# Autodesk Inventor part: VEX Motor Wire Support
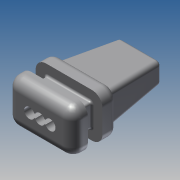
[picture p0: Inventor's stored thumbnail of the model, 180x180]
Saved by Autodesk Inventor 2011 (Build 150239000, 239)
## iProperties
Created: 2010-08
Part Number: VEX Motor Wire Support
Document SubType Name: Modeling
Density: 1 g/cm^3
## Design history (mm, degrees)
feature "Base1"
body "Solid1"
